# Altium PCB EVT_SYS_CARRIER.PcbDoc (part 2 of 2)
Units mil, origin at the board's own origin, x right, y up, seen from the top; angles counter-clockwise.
Board outline 3543.31 x 2755.91 mil, 4 copper layers (Top Layer, Mid-Layer 1, Mid-Layer 2, Bottom Layer), stack 63.036 mil thick; 105 components, 66 nets, 607 pads, 200 vias.
Unrouted connection lines stored in the file: 138.
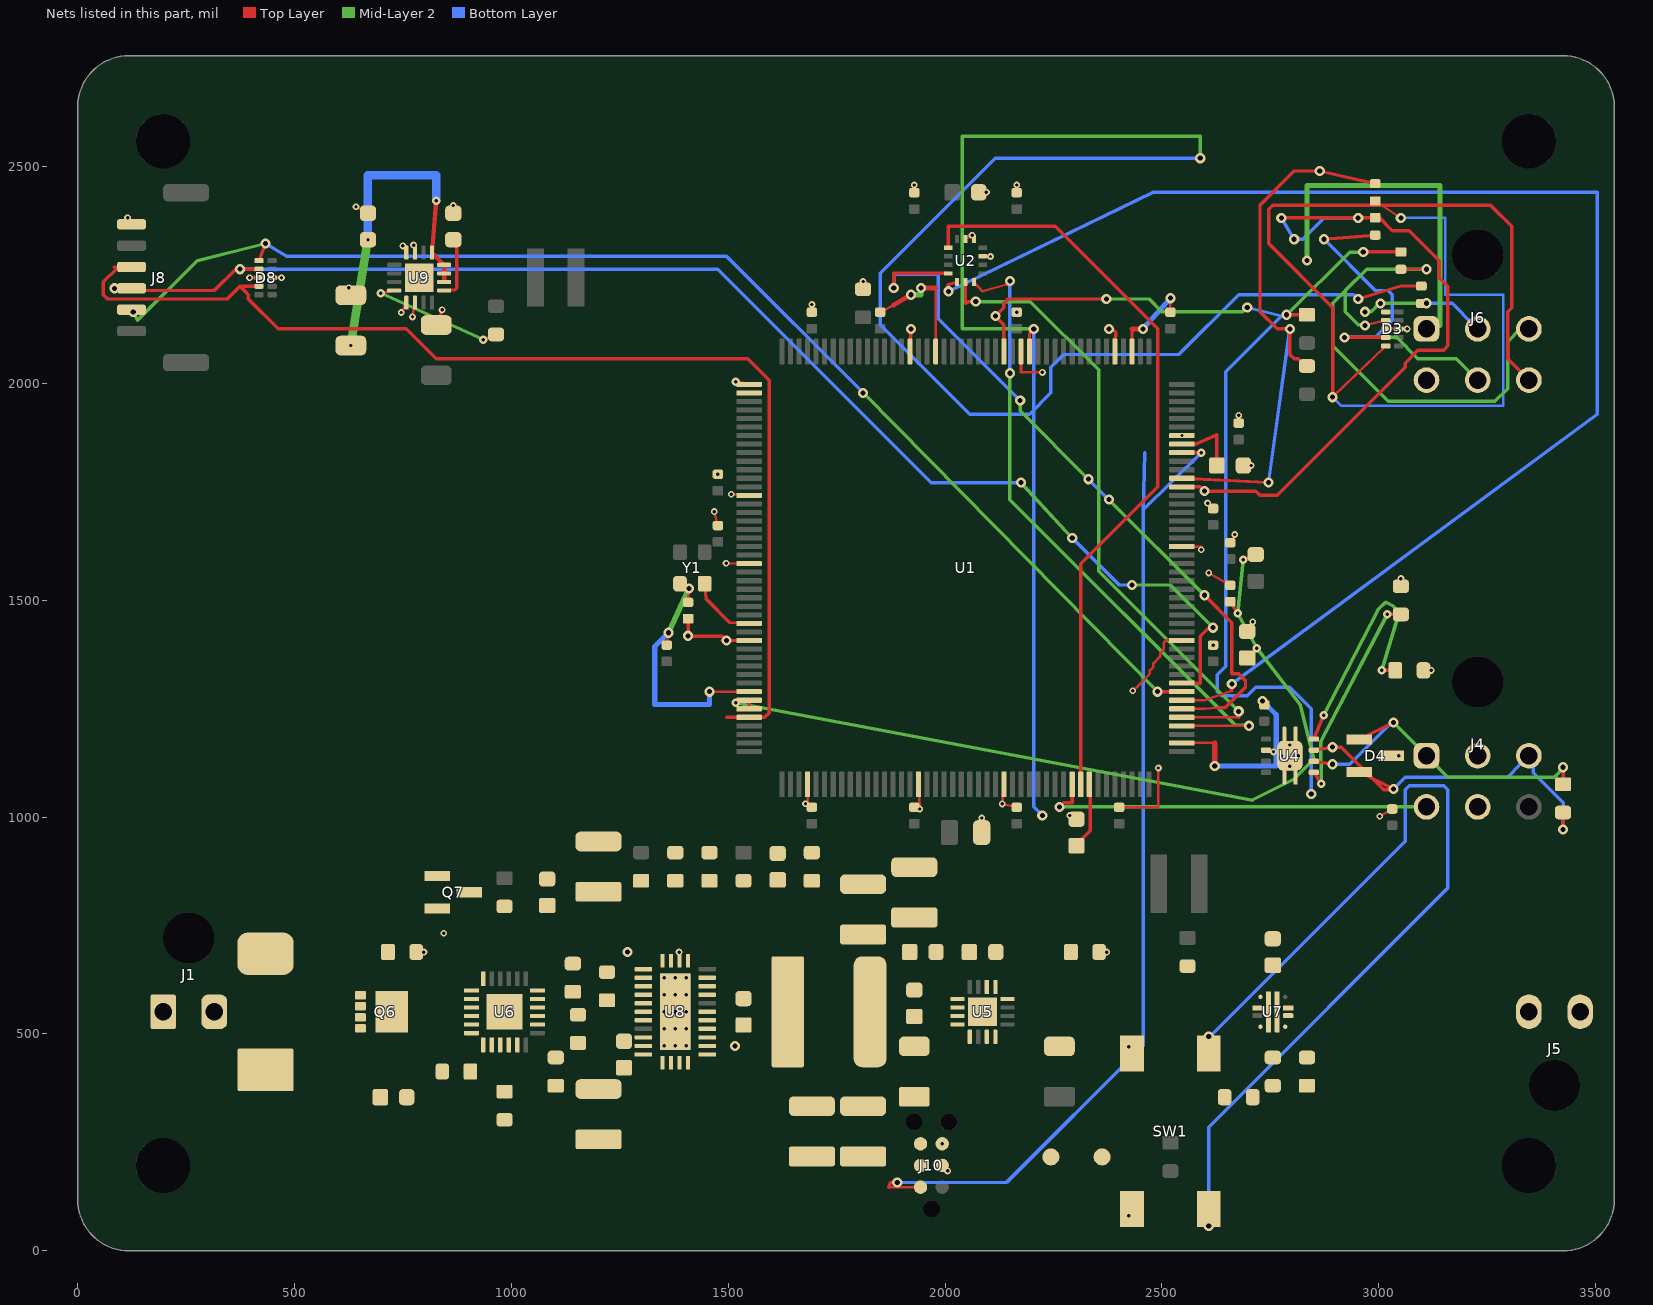
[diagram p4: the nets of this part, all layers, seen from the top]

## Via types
v1: diameter 23.62, hole 11.81, Top Layer to Bottom Layer, 90 vias
v2: diameter 15.75, hole 7.87, Top Layer to Bottom Layer, 89 vias
v3: diameter 19.68, hole 7.87, Top Layer to Bottom Layer, 18 vias
v4: diameter 15.75, hole 7.87, Top Layer to Mid-Layer 1, 2 vias
v5: diameter 11.81, hole 7.09, Top Layer to Mid-Layer 1, 1 vias

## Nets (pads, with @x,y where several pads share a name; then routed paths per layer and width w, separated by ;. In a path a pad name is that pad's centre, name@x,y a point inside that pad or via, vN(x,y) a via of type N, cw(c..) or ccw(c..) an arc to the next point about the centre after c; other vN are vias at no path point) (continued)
GND: C1.2 C2.2 C3.2 C4.2 C6D.2 C6I.2 C7D.2 C10.2 C11.2 C12.2 C13.2 C14.2 C15.2 C20.2 C21.2 C22.2 C40.2 C90.2 C91.2 C92.2 C93.2 C100.2 C101.2 C102.2 C103.2 C104.2 C105.2 C106.2 C107.2 C108.2 C109.2 C110.2 C111.2 C112.2 C113.2 C114.2 C115.2 C800.2 C801.2 C802.2 C803.2 C804.2 C806.2 C807.2 C808.2 C809.2 D1.2 D3.3 D3.8 D4.3 D8.3 D8.8 J1.2 J4.2 J4.5 J5.2 J6.1 J6.4 J8.6 J10.3 J10.5 R1.2 R2.2 R10.2 R41.2 R42.2 R63.2 R73.2 R801.2 R802.2 R805.2 SW1.2 U1.14 U1.22 U1.37 U1.48 U1.61 U1.71 U1.90 U1.102 U1.113 U1.126 U1.135 U1.148 U1.158 U2.6 U2.7 U2.9 U4.2 U4.9 U5.5 U5.6 U5.15 U5.16 U5.17 U6.8 U6.11 U6.25 U7.8 U8.13 U8.14 U8.15 U8.17 U8.19 U8.24 U8.25 U8.26 U8.27 U8.28 U8.29 U8.30 U8.31 U9.5 U9.6 U9.15 U9.16 U9.17 Y1.2 | length 4111
  Top Layer w5.91: v2(114.99,2382.37) J8.6@124.02,2367.13 ; v2(396.26,2244.09) D8.3@417.91,2244.09 ; D8.8@448.23,2244.09 v2(469.88,2244.09) ; v2(625.34,2220.85) C90.2@629.92,2203.74 ; v2(641.73,2407.48) C93.2@669.29,2392.72 ; v2(746.2,2163.75) U9.5@757.87,2186.52 ; v2(749.79,2317.44) U9.16@757.87,2301.67 ; v2(771.92,2153.53) U9.6@777.56,2186.52 ; v2(774.57,2319.14) U9.15@777.56,2301.67 ; R1.2@780.51,688.98 v2(798.23,688.98) ; U9.17@787.4,2244.09 v2(805.12,2244.09) ; C91.2@826.77,2134.84 v2(840.19,2169.76) ; C92.2@866.14,2392.72 v2(866.14,2410.43) ; C115.2@1407.48,1495.28 v1(1409.45,1527.56) ; v1(1456.69,1289.37) U1.37@1548.23,1289.37 ; v2(1467.72,1704.77) C101.2@1476.38,1672.44 ; v2(1495.09,1585.69) U1.22@1548.23,1584.65 ; v2(1506.97,1744.68) U1.14@1548.23,1742.13 ; U1.48@1683.07,1075.79 1683.07,1030.77 v2(1678.24,1030.77) C103.2@1692.91,1022.83 ; C15.2@1692.91,2164.57 v2(1692.91,2182.28) ; R10.2@1811.02,2217.52 v2(1811.02,2235.24) ; C113.2@1850.39,2164.57 1881.89,2181.1 ; C104.2@1929.13,1022.83 v2(1941.72,1018.77) U1.61@1938.98,1075.79 ; C20.2@1929.13,2440.16 v2(1929.13,2457.87) ; U1.158@1978.35,2073.82 1978.35,2220.47 ; J10.3@1993.5,196.85 v2(2006.03,184.32) ; U2.6@2047.24,2333.17 v2(2062.59,2342.03) U2.7@2066.93,2333.17 ; C21.2@2077.76,2440.94 v2(2095.47,2440.95) ; C12.2@2084.65,964.57 v2(2084.65,998.03) ; U2.9@2087.11,2293.31 v2(2104.82,2292.96) ; U1.71@2135.83,1075.79 v2(2131.93,1030.68) C105.2@2165.35,1022.83 ; C22.2@2165.35,2440.16 v2(2165.35,2457.87) ; U1.148@2175.2,2073.82 2175.2,2025.63 v4(2224.41,2025.63) ; v2(2287.81,1003.94) C10.2@2303.15,995.08 ; R2.2@2355.31,688.98 v2(2373.03,688.98) ; C106.2@2401.57,1022.83 2492.05,1022.84 v2(2492.05,1113.31) ; v2(2423.25,80.58) SW1.2@2431.1,96.46 ; v2(2423.25,470.6) SW1.2@2431.1,454.72 ; U1.135@2431.1,2073.82 2431.1,2125.98 ; v2(2433.07,1291.34) 2472.44,1330.71 2472.44,1338.58 2480.32,1346.46 2480.32,1354.33 2496.06,1370.08 2496.06,1377.95 2503.94,1385.83 2503.94,1401.57 2511.81,1409.45 2527.56,1409.45 U1.102@2546.26,1407.48 ; C111.2@2519.69,2164.57 v1(2519.68,2196.85) ; U1.90@2546.26,1171.26 2622.05,1171.26 ; U1.113@2546.26,1624.02 2590.93,1624.02 v2(2590.93,1616.65) ; v2(2605.58,1724.34) C109.2@2618.11,1711.81 ; v2(2608.04,1563.19) C13.2@2657.48,1534.65 ; C114.2@2657.48,1633.07 v2(2668.31,1651.82) ; C110.2@2677.17,1908.66 v2(2677.16,1926.38) ; C11.2@2687.99,1811.02 v2(2705.71,1811.02) ; C14.2@2696.85,1428.15 v2(2709.65,1450.31) ; U4.2@2740.16,1154.53 v2(2757.41,1150.52) ; v2(3002.51,1002.17) C40.2@3031.5,1018.9 ; D3.3@3016.34,2125.98 v2(3065.55,2125.98) D3.8@3046.65,2125.98 ; D4.3@3029.04,1141.73 v2(3046.75,1141.73) ; R42.2@3051.18,1532.48 v2(3051.18,1550.2) ; R41.2@3103.35,1338.58 v2(3121.06,1338.58) ; C102.2@1358.27,1396.85 v1(1362.2,1425.2) C102.2@1358.27,1396.85
  Top Layer w11.81: 1881.89,2181.1 v1(1921.26,2204.72) ; v1(1944.88,2220.47) 1978.35,2220.47 ; 2431.1,2125.98 v1(2456.69,2125.98) ; v1(2622.05,1118.11) 2622.05,1171.26
  Mid-Layer 2 w11.81: v1(1362.2,1425.2) v1(1409.45,1527.56) ; v1(1921.26,2204.72) 1944.88,2204.72 v1(1944.88,2220.47) ; v1(2834.65,2283.46) 2834.65,2456.69 3141.73,2456.69 3141.73,2133.86
  Bottom Layer w11.81: v1(1362.2,1425.2) 1330.71,1393.7 1330.71,1259.84 1456.69,1259.84 v1(1456.69,1289.37) ; v1(2456.69,2125.98) v1(2519.68,2196.85) ; v1(2622.05,1118.11) 2763.78,1118.11 2763.78,1236.22 v1(2732.28,1267.72)
  other v1: 1515.75,472.44 1267.72,688.98
  other v2: 1993.5,246.85 1386.81,688.98 843.98,732.28 2618.11,1396.85 1476.38,1790.55
  other v4: 2165.35,2164.57
  other v5: 2546.26,1879.92
GNSS_PPS: D8.4 J8.4 U1.40 | length 2730.4
  Top Layer w7.87: J8.4@124.02,2268.7 84.65,2268.7 88.58,2263.78 59.06,2234.25 59.06,2204.72 68.9,2194.88 344.49,2194.88 364.17,2214.57 374.02,2224.41 ; D8.4@417.91,2224.41 374.02,2224.41 ; U1.40@1548.23,1230.31 1496.06,1230.32 1505.91,1230.32 1584.65,1230.32 1594.49,1240.16 1594.49,2007.87 1545.28,2057.09 826.77,2057.09 757.87,2125.98 462.6,2125.98 393.7,2194.88 393.7,2204.72 383.86,2214.57 374.02,2224.41
GNSS_RX_EXT: D8.1 J8.2 U1.96 | length 2967.8
  Top Layer w7.87: J8.2@124.02,2170.28 v1(127.95,2165.35) ; D8.1@417.91,2283.46 v1(433.07,2322.83) ; v1(2490.16,1289.37) U1.96@2546.26,1289.37
  Mid-Layer 2 w7.87: v1(127.95,2165.35) 137.8,2145.67 275.59,2283.46 v1(433.07,2322.83) ; v1(1811.02,1978.35) v1(2490.16,1289.37)
  Bottom Layer w7.87: v1(433.07,2322.83) 482.28,2293.31 1496.06,2293.31 v1(1811.02,1978.35)
GNSS_TX_EXT: D8.2 J8.3 U1.97 | length 3171.7
  Top Layer w7.87: J8.3@124.02,2219.49 v1(84.65,2219.49) 98.43,2214.57 314.96,2214.57 364.17,2263.78 v1(374.02,2263.78) D8.2@417.91,2263.78 ; U1.97@2546.26,1309.06 2588.58,1309.06 2588.58,1417.32 2608.27,1437.01 v1(2618.11,1437.01)
  Mid-Layer 2 w7.87: v1(2175.2,1771.65) v1(2293.31,1643.7) ; v1(2431.1,1535.43) 2519.68,1535.43 2608.27,1446.85 v1(2618.11,1437.01)
  Bottom Layer w7.87: v1(374.02,2263.78) 383.86,2263.78 1476.38,2263.78 1968.5,1771.65 2165.35,1771.65 v1(2175.2,1771.65) ; v1(2293.31,1643.7) 2401.57,1535.43 v1(2431.1,1535.43)
HOST_UART1_RX: R600.2 R602.2 TP2.1 U1.150 | length 2558.4
  Top Layer w7.87: U1.150@2135.83,2073.82 2135.83,2086.61 2135.83,2135.83 v1(2116.14,2155.51) 2135.83,2175.2 2135.83,2185.04 2145.67,2194.88 v1(2372.05,2194.88) ; v1(2787.4,2158.46) R600.2@2834.65,2158.46 ; v1(2964.57,2303.54) R602.2@3051.18,2303.54
  Mid-Layer 2 w7.87: v1(2372.05,2194.88) 2470.47,2194.88 2500,2165.35 2687.01,2165.35 v1(2696.85,2175.2) ; v1(2787.4,2158.46) 2795.28,2165.35 2933.07,2303.15 2952.76,2303.15 v1(2964.57,2303.54)
  Bottom Layer w7.87: v1(2696.85,2175.2) 2775.59,2155.51 ; v1(2844.49,1053.15) 2844.49,1062.99 2844.49,1250 2795.28,1299.21 2716.54,1299.21 2696.85,1279.53 2637.8,1279.53 2627.95,1289.37 2627.95,1328.74 2647.64,1348.43 2647.64,2027.56 2775.59,2155.51 ; 2775.59,2155.51 v1(2787.4,2158.46) 2775.59,2155.51
HOST_UART1_RX_EXT: D3.2 J6.3 R602.1 | length 1403.1
  Top Layer w5.91: v1(2968.5,2133.86) D3.2@3016.34,2145.67 ; R602.1@3051.18,2263.39 v1(3110.24,2263.39)
  Mid-Layer 2 w7.87: v1(2968.5,2133.86) 2962.6,2135.83 2952.76,2135.83 2923.23,2165.35 2923.23,2214.57 2972.44,2263.78 ; J6.3@3336.61,2135.83 3326.77,2125.98 3297.24,2096.46 3297.24,1988.19 3267.72,1958.66 3021.65,1958.66 2893.7,2086.61 2893.7,2185.04 2972.44,2263.78 ; 2972.44,2263.78 v1@3100.39,2263.78 ; 2972.44,2263.78 v1@3100.39,2263.78 ; v1@3100.39,2263.78 v1(3110.24,2263.39) v1@3100.39,2263.78
HOST_UART1_TX: R601.2 TP1.1 U1.147 | length 4852.8
  Top Layer w7.87: U1.147@2194.88,2073.82 2194.88,2116.14 v1(2204.72,2125.98) ; v1(2952.76,2194.88) 3051.18,2224.8 R601.2@3098.43,2224.8
  Mid-Layer 2 w7.87: v1(2204.72,2125.98) 2039.37,2125.98 2039.37,2570.08 2588.58,2570.08 v1(2588.58,2519.68)
  Bottom Layer w7.87: v1(2204.72,2125.98) 2204.72,2116.14 2204.72,1023.62 2214.57,1013.78 v1(2224.41,1003.94) ; v1(2588.58,2519.68) 2116.14,2519.68 1850.39,2253.94 1850.39,2135.83 2057.09,1929.13 2194.88,1929.13 2244.09,1978.35 2244.09,2037.4 2273.62,2066.93 2539.37,2066.93 2677.17,2204.72 2942.91,2204.72 v1(2952.76,2194.88)
HOST_UART1_TX_EXT: D3.1 J6.2 R601.1 | length 289.6
  Top Layer w7.87: R601.1@3098.43,2184.65 v1(3110.24,2185.04)
  Mid-Layer 2 w7.87: v1(2968.5,2165.35) 2982.28,2165.35 2992.13,2175.2 v1(3003.94,2184.65) 3011.81,2185.04 v1(3110.24,2185.04)
  Bottom Layer w7.87: v1(3110.24,2185.04) 3169.29,2185.04 J6.2@3218.5,2135.83
HOST_UART2_RX: R604.2 R605.2 U1.121 | length 1299.4
  Top Layer w7.87: U1.121@2546.26,1781.5 v1(2746.06,1771.65) ; R605.2@2834.65,2040.35 2824.8,2047.24 2814.96,2057.09 2805.12,2057.09 2795.28,2066.93 2795.28,2116.14 v1(2795.28,2125.98) 2785.43,2125.98 2765.75,2125.98 2726.38,2165.35 2726.38,2411.42 2805.12,2490.16 2854.33,2490.16 v1(2864.17,2490.16) R604.2@2992.13,2461.02
  Bottom Layer w7.87: v1(2746.06,1771.65) v1(2795.28,2125.98)
HOST_UART2_RX_EXT: D3.5 J6.6 R604.1 | length 2770.7
  Top Layer w5.91: v1(2893.7,1968.5) D3.5@3016.34,2086.61 ; R604.1@2992.13,2420.87 v1(3051.18,2381.89)
  Top Layer w7.87: v1(2893.7,1968.5) 2893.7,1978.35 2893.7,2175.2 2746.06,2322.83 2746.06,2401.57 2755.91,2411.42 3257.87,2411.42 3307.09,2362.2 3307.09,2175.2 3297.24,2165.35 3297.24,2057.09 3336.61,2017.72 J6.6@3346.46,2007.87
  Bottom Layer w5.91: v1(2893.7,1968.5) 2913.39,1948.82 3153.54,1948.82 3287.4,1948.82 3287.4,2204.72 3153.54,2204.72 3153.54,2381.89 v1(3051.18,2381.89)
HOST_UART2_TX: R603.2 U1.120 | length 1644.5
  Top Layer w7.87: U1.120@2546.26,1761.81 2588.58,1761.81 v1(2598.43,1751.97) 2608.27,1751.97 2716.54,1751.97 2726.38,1742.13 2765.75,1742.13 3061.02,2037.4 3061.02,2047.24 3090.55,2076.77 3149.61,2076.77 3159.45,2086.61 3159.45,2224.41 3139.76,2244.09 3139.76,2283.46 3070.87,2352.36 3031.5,2352.36 3001.97,2381.89 2785.43,2381.89 v1(2775.59,2381.89) ; v1(2952.76,2381.89) R603.2@2992.13,2382.28
  Bottom Layer w7.87: v1(2775.59,2381.89) v1(2805.12,2332.68) 2814.96,2332.68 2824.8,2332.68 2874.02,2381.89 2942.91,2381.89 v1(2952.76,2381.89)
HOST_UART2_TX_EXT: D3.4 J6.5 R603.1 | length 943.6
  Top Layer w7.87: v1(2874.02,2332.68) R603.1@2992.13,2342.13 ; v1(2921.26,2106.3) D3.4@3016.34,2106.3
  Mid-Layer 2 w7.87: v1(2921.26,2106.3) 2933.07,2106.3 3041.34,2106.3 3090.55,2057.09 3179.13,2057.09 3208.66,2027.56 J6.5@3218.5,2017.72
  Bottom Layer w7.87: v1(2874.02,2332.68) 2992.13,2214.57 3021.65,2214.57 3031.5,2204.72 3031.5,2145.67 2992.13,2106.3 2933.07,2106.3 v1(2921.26,2106.3)
IMU_DRDY: U1.80 U2.4 | length 1752.9
  Top Layer w7.87: U2.4@2007.87,2312.99 2007.87,2362.2 2253.94,2362.2 2490.16,2125.98 2490.16,1761.81 2312.99,1584.65 U1.80@2312.99,1075.79
IMU_MISO: U1.94 U2.1 | length 1714.6
  Top Layer w5.91: U1.94@2546.26,1250 2598.43,1250 2629.92,1251.97
  Top Layer w7.87: v1(1881.89,2220.47) 1881.89,2253.94 U2.1@2007.38,2253.94 ; v1(2598.43,1511.81) 2661.42,1448.82 2661.42,1330.71 2677.17,1330.71 2692.91,1314.96 2692.91,1299.21 2645.67,1251.97 2629.92,1251.97
  Mid-Layer 2 w7.87: v1(2173.23,1960.63) 2173.23,1937.01 v1(2330.71,1779.53) ; v1(2377.95,1732.28) v1(2598.43,1511.81)
  Bottom Layer w7.87: v1(1881.89,2220.47) 1881.89,2251.97 1984.25,2251.97 1984.25,2181.1 1984.25,2149.61 v1(2173.23,1960.63) ; v1(2330.71,1779.53) v1(2377.95,1732.28)
IMU_MOSI: U1.95 U2.14 | length 3278.1
  Top Layer w5.91: U1.95@2546.26,1269.68 2598.43,1269.68 2661.42,1291.34
  Top Layer w7.87: v1(2007.87,2212.6) 2007.87,2228.35 U2.14@2027.56,2233.76 ; 2661.42,1291.34 v1(2661.42,1307.09)
  Bottom Layer w7.87: v1(2007.87,2212.6) 2480.32,2440.94 3307.09,2440.94 3503.94,2440.94 3503.94,1929.13 v1(2661.42,1307.09)
IMU_NSS: U1.92 U2.12 | length 1522.3
  Top Layer w5.91: U2.12@2066.93,2233.76 2086.61,2212.6 v1@2141.73,2228.35 ; U1.92@2546.26,1210.63 2598.43,1210.63 v1(2700.79,1210.63)
  Top Layer w7.87: v1@2141.73,2228.35 v1(2149.61,2236.22)
  Mid-Layer 2 w7.87: v1(2149.61,2023.62) 2149.61,1732.28 2669.29,1212.6 v1@2700.79,1212.6
  Bottom Layer w7.87: v1(2149.61,2023.62) v1(2149.61,2236.22)
IMU_SCK: U1.93 U2.13 | length 1487.8
  Top Layer w5.91: U1.93@2546.26,1230.31 2598.43,1230.32 2677.17,1230.32
  Top Layer w7.87: U2.13@2047.24,2233.76 2047.24,2185.04 2055.12,2188.98 v1(2070.87,2188.98) ; 2677.17,1230.32 v1(2677.17,1244.09)
  Mid-Layer 2 w7.87: v1(2070.87,2188.98) 2196.85,2188.98 2354.33,2031.5 2354.33,1566.93 v1(2677.17,1244.09)
MCU_HSE_25M: U1.29 Y1.3 | length 156.9
  Top Layer w7.87: Y1.3@1445.87,1538.39 1448.82,1503.94 1503.94,1448.82 U1.29@1548.23,1446.85
NRST: C115.1 SW1.1 U1.31 | length 2302
  Top Layer w7.87: C115.1@1407.48,1457.48 v1(1407.48,1418.11) 1417.32,1417.32 1486.22,1417.32 v1(1496.06,1407.48) ; v1@1486.22,1407.48 v1(1496.06,1407.48) ; U1.31@1548.23,1407.48 v1(1496.06,1407.48)
  Mid-Layer 2 w7.87: v1@2598.43,492.13 v1(2608.27,494.09)
  Bottom Layer w7.87: v1(2608.27,57.09) 2608.27,68.9 2608.27,285.43 3159.45,836.61 3159.45,1062.99 3149.61,1072.83 3070.87,1072.83 3061.02,1062.99 3061.02,944.88 2618.11,501.97 v1(2608.27,494.09)
RADAR_12V: J5.1 U7.6
RADAR_CANH: D4.1 J4.3 R40.1 U4.7 | length 899.8
  Top Layer w7.87: U4.7@2850.39,1154.53 v1(2893.7,1161.42) 2903.54,1161.42 2913.39,1161.42 3011.81,1062.99 3021.65,1062.99 v1(3033.96,1064.96) D4.1@2955.22,1104.33 ; v1(3425.2,971.46) R40.1@3425.2,1010.83
  Mid-Layer 2 w7.87: J4.3@3336.61,1131.89 J4.3@3346.46,1141.73
  Bottom Layer w7.87: v1(3033.96,1064.96) 3041.34,1072.83 3061.02,1092.52 3297.24,1092.52 3326.77,1122.05 J4.3@3336.61,1131.89 ; J4.3@3346.46,1141.73 3356.3,1131.89 3356.3,1122.05 3356.3,1102.36 3425.2,1033.46 3425.2,984.25 v1(3425.2,971.46)
RADAR_CANL: D4.2 J4.1 R40.2 U4.6 | length 804.5
  Top Layer w7.87: U4.6@2850.39,1128.94 v1(2893.7,1122.05) ; D4.2@2955.22,1179.13 v1(3033.96,1218.5) ; R40.2@3425.2,1075.79 v1(3425.2,1115.16)
  Mid-Layer 2 w7.87: v1(3033.96,1218.5) 3041.34,1210.63 3100.39,1151.57 J4.1@3110.24,1141.73 3120.08,1131.89 3159.45,1092.52 3405.51,1092.52 3415.35,1102.36 v1(3425.2,1115.16)
  Bottom Layer w7.87: v1(2893.7,1122.05) 2903.54,1122.05 2933.07,1122.05 3021.65,1210.63 v1(3033.96,1218.5)
RADAR_EFUSE_FLT: R7F.1 U1.2 U7.4
RADAR_REF: J4.4 U1.79 | length 922.4
  Top Layer w7.87: v1(2263.78,1023.62) 2273.62,1033.46 2293.31,1033.46 U1.79@2293.31,1075.79
  Mid-Layer 2 w7.87: v1(2263.78,1023.62) 3090.55,1023.62 3100.39,1023.62 J4.4@3100.39,1013.78
SHDN_PD: R42.1 U4.5 | length 491
  Top Layer w7.87: U4.5@2850.39,1103.35 v3(2867.87,1077.17) ; v3(3019.68,1467.52) R42.1@3051.18,1467.52
  Mid-Layer 2 w7.87: v3(2867.87,1077.17) 2866.14,1173.23 v3(3019.68,1467.52)
STB_PD: R41.1 U4.8 | length 569
  Top Layer w7.87: U4.8@2850.39,1180.12 v3(2872.99,1234.68) ; v3(3006.89,1338.58) R41.1@3038.39,1338.58
  Mid-Layer 2 w7.87: v3(2872.99,1234.68) 3000,1480.32 3015.75,1496.06 3031.5,1488.19 3047.24,1472.44 v3(3006.89,1338.58)
SWCLK: J10.4 U1.137 | length 63.3
  Top Layer w7.87: v1(2377.95,2125.98) 2385.83,2125.98 2393.7,2118.11 U1.137@2391.73,2073.82
SWDIO: J10.2 U1.124 | length 2530.2
  Top Layer w5.91: 1870.08,146.85 J10.2@1943.5,146.85
  Top Layer w7.87: 1870.08,146.85 1874.02,157.48 v1(1889.76,157.48) ; U1.124@2546.26,1840.55 v3(2590.55,1840.55)
  Bottom Layer w7.87: v1(1889.76,157.48) 2141.73,157.48 2456.69,472.44 2456.69,1708.66 ; v3(2590.55,1840.55) 2456.69,1708.66 ; 2456.69,1708.66 2460.63,1840.55 2456.69,1708.66
SWO: J10.6 U1.161 | length 52.2
  Top Layer w7.87: U1.161@1919.29,2073.82 1921.26,2118.11 v1(1921.26,2125.98)
SYS_EFUSE_FLT: R6F.1 U1.1 U6.14 | length 31.5
  Top Layer w7.87: v3(1517.32,2004.17) U1.1@1548.23,1998.03
U5_PG: R5P.1 U5.4
U5_SS_LOCAL: C3.1 U5.9
U6_BGATE: Q6.4 Q7.3 U6.3
U6_DRV: Q7.1 U6.4
U6_DVDT: C6D.1 U6.9
U6_ILIM_LOCAL: R1.1 U6.10
U6_IN_BLOCKED: Q6.5 U6.1 U6.2
U6_OVP_LOCAL: R62.2 R63.1 U6.7
U6_PGTH_LOCAL: R804.2 R805.1 U6.15
U6_UVLO_LOCAL: R61.2 R62.1 U6.6
U7_DVDT: C7D.1 U7.7
U7_ILIM_LOCAL: R2.1 U7.9
U7_OVLO_LOCAL: R72.2 R73.1 U7.2
U7_UVLO_LOCAL: R71.2 R72.1 U7.1
U8_BOOT: C805.1 U8.6
U8_ENABLE: R806.1 U6.16 U8.18
U8_FB_LOCAL: R800.2 R801.1 U8.12
U8_PGOOD: R803.1 U8.16
U8_RT_LOCAL: R802.1 U8.10
U8_SW: C805.2 L8.1 U8.1 U8.2 U8.3 U8.4 U8.5
U8_VCC: C803.1 U8.8
U9_PG: R90.1 U9.4 | length 322.7
  Top Layer w7.87: v3(698.94,2208.43) U9.4@729.82,2214.57 ; v3(935.47,2101.14) R90.1@964.57,2113.19
  Mid-Layer 2 w7.87: v3(698.94,2208.43) v3(935.47,2101.14)
U9_SS_LOCAL: C92.1 U9.9 | length 144.2
  Top Layer w7.87: U9.9@844.98,2214.57 870.08,2216.54 874.02,2220.47 874.02,2318.9 C92.1@866.14,2331.69
V12_SYS: C1.1 C4.1 C90.1 C93.1 C804.1 C806.1 C807.1 C808.1 C809.1 L8.2 R71.1 R800.1 U5.10 U5.11 U5.12 U5.13 U7.5 U8.9 U9.10 U9.11 U9.12 U9.13 | length 811.4
  Top Layer w9.84: v3(826.77,2421.26) U9.13@816.93,2301.67 U9.12@844.98,2273.62 U9.10@844.98,2234.25
  Mid-Layer 2 w19.68: v3(629.92,2087.6) v3(669.29,2331.69)
  Bottom Layer w19.68: v3(669.29,2331.69) 669.29,2480.32 826.77,2480.32 v3(826.77,2421.26)
VCAP1_LOCAL: C10.1 U1.81 | length 155.2
  Top Layer w7.87: C10.1@2303.15,934.06 2303.15,937.01 2334.65,968.5 2334.65,1070.87 U1.81@2332.68,1075.79
VCAP2_LOCAL: C11.1 U1.125 | length 156.2
  Top Layer w7.87: U1.125@2546.26,1860.24 2578.74,1860.24 2626.97,1881.89 C11.1@2626.97,1811.02
VDDA_FILTERED: C13.1 C14.1 FB1.2 U1.38 U1.39 | length 2040
  Top Layer w7.87: v3(1517.32,1263.54) U1.38@1548.23,1269.68 U1.39@1548.23,1250 ; C13.1@2657.48,1496.85 v3(2674.96,1470.67) ; v3(2687.44,1593.74) FB1.2@2716.54,1605.81 ; C14.1@2696.85,1367.13 v3(2719.13,1389.41)
  Mid-Layer 2 w7.87: v3(1517.32,1263.54) 2708.66,1039.37 2803.15,1086.61 2818.9,1102.36 2850.39,1133.86 2818.9,1259.84 v3(2719.13,1389.41) v3(2674.96,1470.67) v3(2687.44,1593.74)
VIN_PROTECTED_24V: C800.1 C801.1 C802.1 R804.1 R806.2 U6.17 U6.18 U6.24 U8.20 U8.21 U8.22
VIN_RAW: C6I.1 D1.1 J1.1 Q6.1 Q6.2 Q6.3 Q7.2 R61.1 U6.5
pads on no net: D3.6 D3.7 D3.9 D3.10 D8.5 D8.6 D8.7 D8.9 D8.10 J1.Un1 J4.6 J4.Un1 J5. J6.Un1 J8.5 J8.MP J10.Un1 J10.Un2 J10.Un3 Q6.Un1 Q6.Un2 Q6.Un3 Q6.Un4 Q6.Un5 Q6.Un6 Q6.Un7 Q6.Un8 U1.3 U1.4 U1.5 U1.7 U1.8 U1.9 U1.10 U1.11 U1.12 U1.13 U1.16 U1.17 U1.18 U1.19 U1.20 U1.21 U1.24 U1.25 U1.26 U1.27 U1.28 U1.30 U1.32 U1.33 U1.34 U1.35 U1.41 U1.42 U1.43 U1.44 U1.45 U1.46 U1.47 U1.50 U1.51 U1.52 U1.53 U1.54 U1.55 U1.56 U1.57 U1.58 U1.59 U1.60 U1.63 U1.64 U1.65 U1.66 U1.67 U1.68 U1.69 U1.70 U1.73 U1.74 U1.75 U1.76 U1.77 U1.78 U1.83 U1.84 U1.85 U1.86 U1.87 U1.88 U1.89 U1.98 U1.99 U1.100 U1.101 U1.104 U1.105 U1.106 U1.107 U1.108 U1.109 U1.110 U1.111 U1.112 U1.115 U1.116 U1.117 U1.118 U1.119 U1.122 U1.123 U1.128 U1.129 U1.130 U1.131 U1.132 U1.133 U1.134 U1.138 U1.139 U1.140 U1.141 U1.144 U1.145 U1.146 U1.151 U1.152 U1.153 U1.154 U1.155 U1.156 U1.157 U1.160 U1.162 U1.163 U1.164 U1.165 U1.167 U1.168 U1.169 U1.170 U1.173 U1.174 U1.175 U1.176 U2.2 U2.3 U2.10 U2.11 U4.Un1 U4.Un2 U4.Un3 U4.Un4 U4.Un5 U5.7 U5.8 U5.Un1 U5.Un2 U5.Un3 U5.Un4 U6.12 U6.13 U6.19 U6.20 U6.21 U6.22 U6.23 U6.Un1 U6.Un2 U6.Un3 U6.Un4 U7.3 U7.10 U7.Un1 U7.Un2 U7.Un3 U7.Un4 U8.7 U8.11 U8.23 U8.Un1 U8.Un2 U8.Un3 U8.Un4 U8.Un5 U8.Un6 U8.Un7 U8.Un8 U9.7 U9.8 U9.Un1 U9.Un2 U9.Un3 U9.Un4 Y1.1

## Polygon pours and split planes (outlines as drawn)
GND on Mid-Layer 1 "EVT_GND_L2_PLANE" (solid, pour order 1): 118.11,0 cw(c118.11,118.11) 0,118.11 0,2637.8 cw(c118.11,2637.8) 118.11,2755.91 3425.2,2755.91 cw(c3425.2,2637.8) 3543.31,2637.8 3543.31,118.11 cw(c3425.2,118.11) 3425.2,0
3V3 on Mid-Layer 2 "EVT_3V3_L3_PLANE" (solid, pour order 2): 118.11,0 cw(c118.11,118.11) 0,118.11 0,2637.8 cw(c118.11,2637.8) 118.11,2755.91 3425.2,2755.91 cw(c3425.2,2637.8) 3543.31,2637.8 3543.31,118.11 cw(c3425.2,118.11) 3425.2,0

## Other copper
Top Layer:
  rectangle net GND: 1342.52,568.9 1371.06,598.43
  rectangle net GND: 1342.52,503.94 1371.06,533.46
  rectangle net 3V3: 2549.21,720.47 2568.9,748.03
  rectangle net 3V3: 1328.74,311.02 1515.75,320.87
  region net U6_IN_BLOCKED: 1285.77,2217.71 1269.2,2217.71 1269.2,2212.19 1285.74,2212.19 1285.74,2192.51 1269.2,2192.51 1269.2,2186.21 1285.74,2186.21 1285.74,2166.52 1269.2,2166.52 1269.2,2161.01 1285.74,2161.01 1285.74,2141.13 1194.4,2141.13 1194.4,2237.59 1285.77,2237.59
  region net BUCK_SW: 2513.78,604.33 2507.87,604.33 2507.87,618.11 2494.09,618.11 2494.09,625.98 2513.78,625.98
  region net BUCK_SW: 2514.53,627.8 2515.17,627.38 2515.6,626.74 2515.75,625.98 2515.75,604.33 2515.6,603.58 2515.17,602.94 2514.53,602.51 2513.78,602.36 2507.87,602.36 2507.12,602.51 2506.48,602.94 2506.06,603.58 2505.91,604.33 2505.91,625.98 2506.06,626.74 2506.48,627.38 2507.12,627.8 2507.87,627.95 2513.78,627.95
  region net BUCK_SW: 2513.78,673.23 2494.09,673.23 2494.09,681.1 2507.87,681.1 2507.87,694.88 2513.78,694.88
  region net BUCK_SW: 2514.53,696.7 2515.17,696.27 2515.6,695.64 2515.75,694.88 2515.75,673.23 2515.6,672.48 2515.17,671.84 2514.53,671.41 2513.78,671.26 2507.87,671.26 2507.12,671.41 2506.48,671.84 2506.06,672.48 2505.91,673.23 2505.91,694.88 2506.06,695.64 2506.48,696.27 2507.12,696.7 2507.87,696.85 2513.78,696.85
Mid-Layer 1:
  rectangle net GND: 1307.09,545.28 1370.08,629.92
  rectangle net GND: 1503.94,472.44 1527.56,629.92
  rectangle net GND: 1255.91,629.92 1279.53,688.98
  rectangle net GND: 1169.29,472.44 1192.91,629.92
  rectangle net GND: 911.42,542.32 938.98,629.92
  rectangle net GND: 299.21,551.18 330.71,602.36
  rectangle net BUCK_SW: 2458.66,629.92 2498.03,728.35
  rectangle net GND: 923.23,600.39 2374.02,659.45
  rectangle net GND: 903.54,629.92 942.91,728.35
  rectangle net GND: 828.74,708.66 923.23,748.03
  rectangle net GND: 809.06,629.92 848.43,728.35
  rectangle net GND: 314.96,600.39 818.9,659.45
Mid-Layer 2:
  rectangle net 3V3: 2547.24,748.03 2570.87,952.76
  rectangle net 3V3: 1444.88,748.03 1468.5,952.76
  rectangle net 3V3: 972.44,748.03 996.06,952.76
  rectangle net 3V3: 1769.68,551.18 1828.74,952.76
  rectangle net 3V3: 984.25,923.23 3149.61,982.28

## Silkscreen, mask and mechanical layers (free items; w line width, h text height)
Top Overlay:
  drawing of 321 lines, arcs and shapes, not listed
Top Paste:
  region: 2570.87,681.1 2584.65,681.1 2584.65,673.23 2564.96,673.23 2564.96,694.88 2570.87,694.88
  region: 2571.62,696.7 2572.26,696.27 2572.68,695.64 2572.83,694.88 2572.83,673.23 2572.68,672.48 2572.26,671.84 2571.62,671.41 2570.87,671.26 2564.96,671.26 2564.21,671.41 2563.57,671.84 2563.14,672.48 2562.99,673.23 2562.99,694.88 2563.14,695.64 2563.57,696.27 2564.21,696.7 2564.96,696.85 2570.87,696.85
  region: 2584.65,618.11 2570.87,618.11 2570.87,604.33 2564.96,604.33 2564.96,625.98 2584.65,625.98
  region: 2571.62,627.8 2572.26,627.38 2572.68,626.74 2572.83,625.98 2572.83,604.33 2572.68,603.58 2572.26,602.94 2571.62,602.51 2570.87,602.36 2564.96,602.36 2564.21,602.51 2563.57,602.94 2563.14,603.58 2562.99,604.33 2562.99,625.98 2563.14,626.74 2563.57,627.38 2564.21,627.8 2564.96,627.95 2570.87,627.95
  region: 2513.78,604.33 2507.87,604.33 2507.87,618.11 2494.09,618.11 2494.09,625.98 2513.78,625.98
  region: 2514.53,627.8 2515.17,627.38 2515.6,626.74 2515.75,625.98 2515.75,604.33 2515.6,603.58 2515.17,602.94 2514.53,602.51 2513.78,602.36 2507.87,602.36 2507.12,602.51 2506.48,602.94 2506.06,603.58 2505.91,604.33 2505.91,625.98 2506.06,626.74 2506.48,627.38 2507.12,627.8 2507.87,627.95 2513.78,627.95
  region: 2513.78,673.23 2494.09,673.23 2494.09,681.1 2507.87,681.1 2507.87,694.88 2513.78,694.88
  region: 2514.53,696.7 2515.17,696.27 2515.6,695.64 2515.75,694.88 2515.75,673.23 2515.6,672.48 2515.17,671.84 2514.53,671.41 2513.78,671.26 2507.87,671.26 2507.12,671.41 2506.48,671.84 2506.06,672.48 2505.91,673.23 2505.91,694.88 2506.06,695.64 2506.48,696.27 2507.12,696.7 2507.87,696.85 2513.78,696.85
Top Solder:
  region: 1285.77,2217.71 1269.2,2217.71 1269.2,2212.19 1285.74,2212.19 1285.74,2192.51 1269.2,2192.51 1269.2,2186.21 1285.74,2186.21 1285.74,2166.52 1269.2,2166.52 1269.2,2161.01 1285.74,2161.01 1285.74,2141.13 1194.4,2141.13 1194.4,2237.59 1285.77,2237.59
  region: 2570.87,681.1 2584.65,681.1 2584.65,673.23 2564.96,673.23 2564.96,694.88 2570.87,694.88
  region: 2571.62,696.7 2572.26,696.27 2572.68,695.64 2572.83,694.88 2572.83,673.23 2572.68,672.48 2572.26,671.84 2571.62,671.41 2570.87,671.26 2564.96,671.26 2564.21,671.41 2563.57,671.84 2563.14,672.48 2562.99,673.23 2562.99,694.88 2563.14,695.64 2563.57,696.27 2564.21,696.7 2564.96,696.85 2570.87,696.85
  region: 2584.65,618.11 2570.87,618.11 2570.87,604.33 2564.96,604.33 2564.96,625.98 2584.65,625.98
  region: 2571.62,627.8 2572.26,627.38 2572.68,626.74 2572.83,625.98 2572.83,604.33 2572.68,603.58 2572.26,602.94 2571.62,602.51 2570.87,602.36 2564.96,602.36 2564.21,602.51 2563.57,602.94 2563.14,603.58 2562.99,604.33 2562.99,625.98 2563.14,626.74 2563.57,627.38 2564.21,627.8 2564.96,627.95 2570.87,627.95
  region: 2513.78,604.33 2507.87,604.33 2507.87,618.11 2494.09,618.11 2494.09,625.98 2513.78,625.98
  region: 2514.53,627.8 2515.17,627.38 2515.6,626.74 2515.75,625.98 2515.75,604.33 2515.6,603.58 2515.17,602.94 2514.53,602.51 2513.78,602.36 2507.87,602.36 2507.12,602.51 2506.48,602.94 2506.06,603.58 2505.91,604.33 2505.91,625.98 2506.06,626.74 2506.48,627.38 2507.12,627.8 2507.87,627.95 2513.78,627.95
  region: 2513.78,673.23 2494.09,673.23 2494.09,681.1 2507.87,681.1 2507.87,694.88 2513.78,694.88
  region: 2514.53,696.7 2515.17,696.27 2515.6,695.64 2515.75,694.88 2515.75,673.23 2515.6,672.48 2515.17,671.84 2514.53,671.41 2513.78,671.26 2507.87,671.26 2507.12,671.41 2506.48,671.84 2506.06,672.48 2505.91,673.23 2505.91,694.88 2506.06,695.64 2506.48,696.27 2507.12,696.7 2507.87,696.85 2513.78,696.85
Mechanical 1:
  lines w3.94: 0,2637.8 cw(c118.11,2637.8) 118.11,2755.91 ; 0,3031.5 cw(c118.11,3031.5) 118.11,3149.61 ; 3136.81,200 3477.36,200 3516.73,239.37 3516.73,589.76 3136.81,589.76 3136.81,239.37 ; 3425.2,0 ccw(c3425.2,118.11) 3543.31,118.11 ; 3425.2,2755.91 cw(c3425.2,2637.8) 3543.31,2637.8 ; 3818.9,0 ccw(c3818.9,118.11) 3937.01,118.11 ; 3818.9,3149.61 cw(c3818.9,3031.5) 3937.01,3031.5 ; 0,118.11 ccw(c118.11,118.11) 118.11,0 cw(c118.11,118.11) 0,118.11 ; 1023.62,2165.35 1181.1,2165.35 1181.1,2322.83 1023.62,2322.83 1023.62,2165.35 ; 1330.89,2145.66 1330.89,2259.83 1382.07,2259.83 1382.07,2145.66 1330.89,2145.66 ; 2401.57,157.48 2637.8,157.48 2637.8,393.7 2401.57,393.7 2401.57,157.48 ; 3045.28,1084.65 3045.28,1198.82 3096.46,1198.82 3096.46,1084.65 3045.28,1084.65
Mechanical 4:
  drawing of 518 lines, arcs and shapes, not listed
Mechanical 6:
  drawing of 408 lines, arcs and shapes, not listed
  text "'.Designator'" at 3714.64,2646.08 h39.37 r180
  text "'.Designator'" at 1623.02,2458.56 h31.5 r90
  text "'.Designator'" at 1740.1,2458.56 h31.5 r90
  text "'.Designator'" at 1857.19,2458.56 h31.5 r90
  text "'.Designator'" at 1974.28,2458.56 h31.5 r90
  text "'.Designator'" at 1374.4,2441.69 h39.37
  text "'.Designator'" at 1983.52,2427.71 h15.75
  text "'.Designator'" at 3069.02,2416.52 h39.37
  text "'.Designator'" at 1096.56,2407.75 h39.37
  text "'.Designator'" at 3000.77,2399.48 h10.24 r90
  text "'.Designator'" at 1937.5,2381.33 h9.84 r90
  text "'.Designator'" at 2173.72,2381.33 h9.84 r90
  text "'.Designator'" at 3000.77,2320.74 h10.24 r90
  text "'.Designator'" at 682.52,2298.48 h15.75 r90
  text "'.Designator'" at 879.38,2298.48 h15.75 r90
  text "'.Designator'" at 3059.82,2242 h10.24 r90
  text "'.Designator'" at 668.01,2219.38 h29.53
  text "'.Designator'" at 1442.26,2187.51 h31.5
  text "'.Designator'" at 3107.07,2163.26 h10.24 r90
  text "'.Designator'" at 1184.28,2162.12 h27.56
  text "'.Designator'" at 451.96,2155.78 h21.65 r90
  text "'.Designator'" at 1622.16,2154.57 h15.75 r90
  text "'.Designator'" at 1672.31,2154.57 h15.75 r90
  text "'.Designator'" at 1722.47,2154.57 h15.75 r90
  text "'.Designator'" at 1772.63,2154.57 h15.75 r90
  text "'.Designator'" at 1823.28,2154.57 h15.75 r90
  text "'.Designator'" at 1874.42,2154.57 h15.75 r90
  text "'.Designator'" at 1925.56,2154.57 h15.75 r90
  text "'.Designator'" at 1976.7,2154.57 h15.75 r90
  text "'.Designator'" at 2027.85,2154.57 h15.75 r90
  text "'.Designator'" at 1090.77,2124.94 h31.5 r90
  text "'.Designator'" at 1824.26,2121.31 h15.75 r90
  text "'.Designator'" at 1701.28,2105.74 h9.84 r90
  text "'.Designator'" at 1858.76,2105.74 h9.84 r90
  text "'.Designator'" at 2173.72,2105.74 h9.84 r90
  text "'.Designator'" at 2528.05,2105.74 h9.84 r90
  text "'.Designator'" at 229.93,2084.77 h39.37 r90
  text "'.Designator'" at 977.8,2081.94 h15.75 r90
  text "'.Designator'" at 1098.54,2076.76 h15.75
  text "'.Designator'" at 2847.88,2062.26 h15.75 r90
  text "'.Designator'" at 3050.38,2037.67 h21.65 r90
  text "'.Designator'" at 656.39,2018.21 h31.5 r90
  text "'.Designator'" at 853.24,2018.21 h31.5 r90
  text "'.Designator'" at 1050.56,2003.11 h15.75 r90
  text "'.Designator'" at 1101.7,2003.11 h15.75 r90
  text "'.Designator'" at 2847.88,1944.15 h15.75 r90
  text "'.Designator'" at 2685.53,1849.84 h9.84 r90
  text "'.Designator'" at 2593.75,1797.79 h15.75
  text "'.Designator'" at 1484.75,1731.72 h9.84 r90
  text "'.Designator'" at 2626.48,1652.98 h9.84 r90
  text "'.Designator'" at 1484.75,1613.61 h9.84 r90
  text "'.Designator'" at 2665.85,1574.24 h9.84 r90
  text "'.Designator'" at 1887.92,1541.72 h39.37
  text "'.Designator'" at 2729.77,1511.07 h15.75 r90
  text "'.Designator'" at 1433.86,1495.14 h19.68 r90
  text "'.Designator'" at 2665.85,1475.82 h9.84 r90
  text "'.Designator'" at 1415.85,1436.45 h9.84 r90
  text "'.Designator'" at 3064.41,1436.27 h15.75 r90
  text "'.Designator'" at 3069.02,1432.27 h39.37
  text "'.Designator'" at 1366.64,1338.02 h9.84 r90
  text "'.Designator'" at 2626.48,1338.02 h9.84 r90
  text "'.Designator'" at 2710.08,1333.91 h15.75 r90
  text "'.Designator'" at 3007.14,1325.35 h15.75
  text "'.Designator'" at 2744.59,1200.23 h9.84 r90
  text "'.Designator'" at 2683.95,1118.77 h27.56
  text "'.Designator'" at 3423.51,1046.63 h28.35 r90
  text "'.Designator'" at 3438.43,979.58 h15.75 r90
  text "'.Designator'" at 1701.28,964.01 h9.84 r90
  text "'.Designator'" at 1937.5,964.01 h9.84 r90
  text "'.Designator'" at 2173.72,964.01 h9.84 r90
  text "'.Designator'" at 2409.94,964.01 h9.84 r90
  text "'.Designator'" at 3039.87,960.07 h9.84 r90
  text "'.Designator'" at 1967.39,947.83 h19.68
  text "'.Designator'" at 2316.38,900.84 h15.75 r90
  text "'.Designator'" at 3781.37,890.56 h39.37 r180
  text "'.Designator'" at 96.58,841.72 h39.37
  text "'.Designator'" at 684.3,675.74 h15.75
  text "'.Designator'" at 1137.06,675.74 h15.75
  text "'.Designator'" at 1274.85,675.74 h15.75
  text "'.Designator'" at 2259.11,675.74 h15.75
  text "'.Designator'" at 879.38,625.25 h15.75 r90
  text "'.Designator'" at 997.49,625.25 h15.75 r90
  text "'.Designator'" at 1469.93,625.25 h15.75 r90
  text "'.Designator'" at 2454.18,625.25 h15.75 r90
  text "'.Designator'" at 2572.29,625.25 h15.75 r90
  text "'.Designator'" at 1457.98,575.9 h29.53 r180
  text "'.Designator'" at 790.04,525.59 h39.37
  text "'.Designator'" at 1494.22,518.1 h39.37
  text "'.Designator'" at 462.59,475.08 h39.37 r90
  text "'.Designator'" at 723.67,400.15 h15.75
  text "'.Designator'" at 2298.48,360.78 h15.75
  text "'.Designator'" at 879.38,349.66 h15.75 r90
  text "'.Designator'" at 958.12,349.66 h15.75 r90
  text "'.Designator'" at 2532.92,349.66 h15.75 r90
  text "'.Designator'" at 1207.57,285.93 h31.5 r90
  text "'.Designator'" at 1542.21,285.93 h31.5 r90
  text "'.Designator'" at 2454.18,270.92 h15.75 r90
  text "'.Designator'" at 3840.42,260.64 h39.37 r180
  text "'.Designator'" at 2788.99,254.06 h39.37 r90
  text "'.Designator'" at 2084.77,240.54 h39.37
  text "'.Designator'" at 2202.88,240.54 h39.37
  text "'.Designator'" at 2532.92,152.81 h15.75 r90
  text "'.Designator'" at 2001.59,37.53 h39.37 r90
Mechanical 7:
  text "KEEPOUT" at 1979.13,147.2 h15.75 r90
Mechanical 15:
  lines w1.97: 1013.39,2155.12 1191.34,2155.12 1191.34,2333.07 1013.39,2333.07 1013.39,2155.12 ; 1280.5,2135.82 1280.5,2269.67 1432.47,2269.67 1432.47,2135.82 1280.5,2135.82 ; 2391.73,45.28 2647.64,45.28 2647.64,505.91 2391.73,505.91 2391.73,45.28 ; 2994.88,1074.8 2994.88,1208.66 3146.85,1208.66 3146.85,1074.8 2994.88,1074.8 ; 3116.93,180.31 3116.93,609.84 3536.61,609.84 3536.61,180.31 3116.93,180.31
